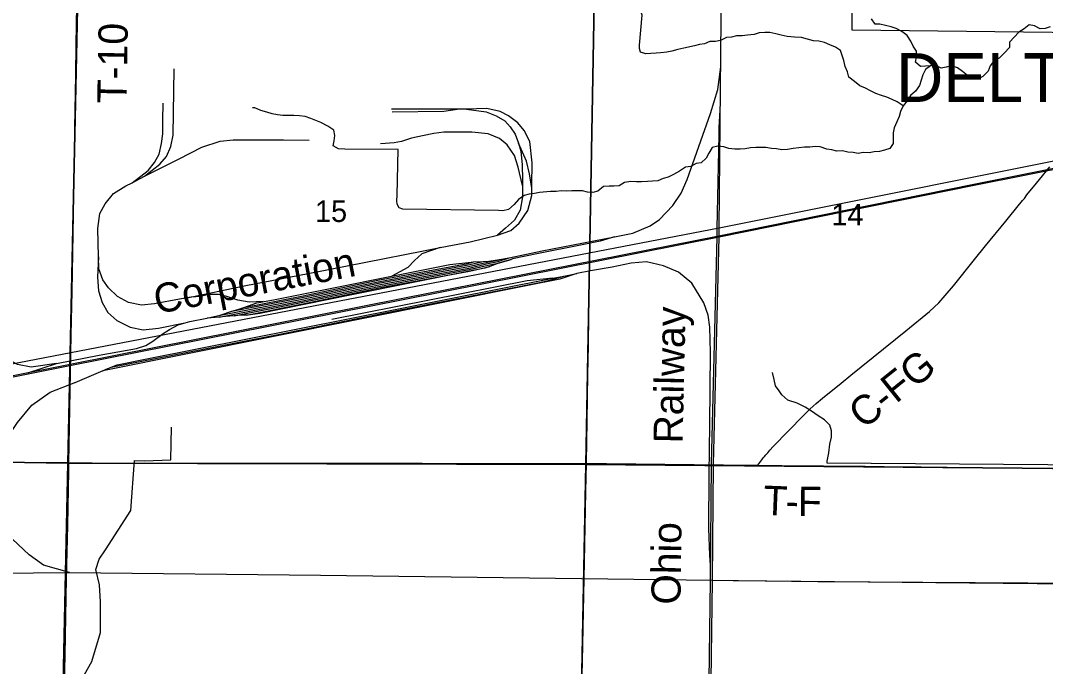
# Model space of a CAD drawing. Extents: x 0 to 42, y 0 to 22.
# Drawn here: x 3.119 to 5.107, y 16.093 to 17.347 of the extents above; entities that cross this region are included whole.
import ezdxf

# ---------------------------------------------------------------- set-up
doc = ezdxf.new("R2010")
doc.units = 0
for name, color, linetype in [('GM_X_Corporation', 7, 'Continuous'), ('GM_X_Corporation_Text', 7, 'Continuous'), ('GM_X_County_Road', 7, 'Continuous'), ('GM_X_County_Road_Text', 7, 'Continuous'), ('GM_X_Minor_River', 7, 'Continuous'), ('GM_X_Rail_Line', 7, 'Continuous'), ('GM_X_Rail_Line_Text', 7, 'Continuous'), ('GM_X_Section', 7, 'Continuous'), ('GM_X_Section_Text', 7, 'Continuous'), ('GM_X_Township_Road', 7, 'Continuous'), ('GM_X_Township_Road_Text', 7, 'Continuous')]:
    doc.layers.add(name, color=color, linetype=linetype)

msp = doc.modelspace()

# ---------------------------------------------------------------- linework, layer by layer
at = {"layer": 'GM_X_Corporation'}
msp.add_lwpolyline([(5.2302, 17.3226), (4.7322, 17.3283), (4.7317, 17.4841)], dxfattribs=at)
at = {"layer": 'GM_X_County_Road'}
for points in [[(4.5493, 16.4842), (4.557, 16.4944), (4.5595, 16.498), (4.5622, 16.501), (4.5648, 16.5039), (4.5685, 16.5081), (4.5724, 16.513), (4.5787, 16.52), (4.6373, 16.5802), (4.6507, 16.5932), (4.6622, 16.6037), (4.6741, 16.6138), (4.7104, 16.6431), (4.7296, 16.6589), (4.8363, 16.7446), (4.8821, 16.782), (4.8912, 16.7903), (4.8999, 16.7991), (4.9122, 16.8131), (4.9281, 16.8322), (4.9692, 16.883), (4.9907, 16.9096), (5.0298, 16.9578), (5.0376, 16.967), (5.0622, 16.9973), (5.0661, 17.0017), (5.0709, 17.0083), (5.0896, 17.0315), (5.1153, 17.0627)], [(2.209, 16.4644), (2.2212, 16.4668), (2.2731, 16.4767), (2.3584, 16.4941), (2.3767, 16.4974), (2.389, 16.499), (2.4013, 16.5001), (2.4137, 16.5007), (2.4355, 16.5009), (2.507, 16.4998), (2.5785, 16.4988), (2.6748, 16.4969), (2.8738, 16.4939), (2.9919, 16.4918), (3.0632, 16.491), (3.0779, 16.4906), (3.1679, 16.4894), (3.2134, 16.4891)], [(3.2134, 16.4891), (3.258, 16.4888), (3.373, 16.488), (3.4476, 16.4882), (3.4787, 16.4881), (3.5284, 16.488), (3.5937, 16.488), (3.6559, 16.4878), (3.7056, 16.4878), (3.7646, 16.4879), (3.8983, 16.4876), (3.9293, 16.4875), (4.0567, 16.4872), (4.0847, 16.4871), (4.2153, 16.4875), (4.2165, 16.4875)], [(4.2165, 16.4875), (4.2557, 16.4872), (4.4826, 16.4845), (4.5493, 16.4842)]]:
    msp.add_lwpolyline(points, dxfattribs=at)
at = {"layer": 'GM_X_Minor_River'}
for points in [[(4.3197, 17.2987), (4.3245, 17.3574), (4.3213, 17.3662), (4.3149, 17.369), (4.2953, 17.3748), (4.2312, 17.391), (4.2268, 17.3975), (4.2247, 17.4075), (4.2193, 17.4194), (4.1864, 17.4402), (4.1477, 17.4395)], [(4.8841, 17.2591), (4.8643, 17.2577), (4.8546, 17.2662), (4.8564, 17.2764), (4.8566, 17.2871), (4.8504, 17.2971), (4.8457, 17.307), (4.8384, 17.3178), (4.8283, 17.3253), (4.8175, 17.3316), (4.8077, 17.3345), (4.7858, 17.3395), (4.7763, 17.3397), (4.7693, 17.3501)], [(5.1161, 17.3348), (5.1062, 17.3316), (5.0967, 17.331), (5.0854, 17.3366), (5.0749, 17.3384), (5.0652, 17.3306), (5.0552, 17.3244), (5.0458, 17.3143), (5.0373, 17.3047), (5.0367, 17.2948), (5.0265, 17.2836), (5.0172, 17.2736), (5.0076, 17.2696), (4.9998, 17.2592), (4.9954, 17.2487), (4.9856, 17.2382), (4.9753, 17.2328), (4.9655, 17.2353), (4.9557, 17.2404), (4.946, 17.2482), (4.9363, 17.2553), (4.9239, 17.259), (4.914, 17.2562), (4.9044, 17.2545)], [(4.8306, 17.181), (4.8194, 17.1888), (4.8093, 17.1936), (4.7992, 17.198), (4.7886, 17.2013), (4.7777, 17.2053), (4.7676, 17.2101), (4.7575, 17.2153), (4.7466, 17.2204), (4.7365, 17.2286), (4.7257, 17.2372), (4.7229, 17.2475), (4.7182, 17.2575), (4.7155, 17.269), (4.7123, 17.2789), (4.7091, 17.2888), (4.6994, 17.2951), (4.6889, 17.2999), (4.678, 17.304), (4.6674, 17.3069), (4.6568, 17.3075), (4.6451, 17.3104), (4.6334, 17.3137), (4.6198, 17.3144), (4.6062, 17.3158), (4.5945, 17.3187), (4.5839, 17.3212), (4.5722, 17.3234), (4.5627, 17.3236), (4.5517, 17.3227), (4.5421, 17.3195), (4.5288, 17.3183), (4.5185, 17.317), (4.5079, 17.3169), (4.498, 17.3144), (4.4881, 17.3139), (4.4766, 17.3081), (4.4671, 17.306), (4.4561, 17.3063), (4.4457, 17.3019), (4.4362, 17.3003), (4.4263, 17.2978), (4.4057, 17.293), (4.3942, 17.2906), (4.3824, 17.2874), (4.3725, 17.2854), (4.3604, 17.2843), (4.3516, 17.2835), (4.3413, 17.283), (4.3318, 17.2821), (4.3217, 17.2854), (4.3196, 17.2924), (4.3197, 17.2987)], [(4.9044, 17.2545), (4.8943, 17.2593), (4.8841, 17.2591), (4.8744, 17.2521), (4.8689, 17.2416), (4.866, 17.2311), (4.8627, 17.2205), (4.8548, 17.21), (4.8452, 17.2012), (4.8385, 17.1907), (4.8306, 17.181), (4.8258, 17.1701), (4.823, 17.1603), (4.8186, 17.1505), (4.8134, 17.1389), (4.8112, 17.1287), (4.8114, 17.118), (4.8115, 17.1085), (4.8052, 17.0984), (4.7949, 17.0952), (4.785, 17.0928), (4.7747, 17.0923), (4.7648, 17.0902), (4.7534, 17.0905), (4.7435, 17.0888), (4.7337, 17.0909), (4.7235, 17.0915), (4.7133, 17.0937), (4.7023, 17.0935), (4.6925, 17.096), (4.6826, 17.0974), (4.6702, 17.1015), (4.66, 17.1024), (4.6497, 17.1011), (4.6395, 17.101), (4.6288, 17.0997), (4.6174, 17.0988), (4.6064, 17.0968), (4.5953, 17.0959), (4.5855, 17.0977), (4.5753, 17.0986), (4.5643, 17.1004), (4.5549, 17.1006), (4.545, 17.1005), (4.5351, 17.0995), (4.5244, 17.0979), (4.5149, 17.097), (4.5043, 17.0972), (4.4926, 17.0986), (4.4828, 17.1015), (4.4714, 17.1029), (4.4604, 17.1004), (4.4541, 17.0896), (4.4489, 17.0795), (4.4392, 17.0709), (4.4297, 17.0693), (4.4189, 17.0638), (4.4086, 17.0621), (4.3971, 17.0548), (4.3856, 17.0478), (4.3752, 17.0428), (4.3656, 17.0403), (4.3549, 17.036), (4.3447, 17.0351), (4.3348, 17.0342), (4.3234, 17.0337), (4.3135, 17.0339), (4.3029, 17.0345), (4.2907, 17.0325), (4.2803, 17.0259), (4.2701, 17.0254), (4.2606, 17.0256), (4.2496, 17.0247), (4.2387, 17.0158), (4.2288, 17.013), (4.2186, 17.0136), (4.2088, 17.0161), (4.1883, 17.0166), (4.1784, 17.0157), (4.1674, 17.0163), (4.1579, 17.015), (4.1469, 17.0148), (4.1256, 17.013), (4.1157, 17.0114), (4.1058, 17.0101), (4.0959, 17.0073), (4.0851, 16.9995), (4.0765, 16.9899), (4.0655, 16.9799), (4.0546, 16.9777), (4.0459, 16.978)], [(3.7485, 17.097), (3.7361, 17.098), (3.7259, 17.1036), (3.7277, 17.1134), (3.7287, 17.1236), (3.727, 17.1339), (3.7154, 17.1418), (3.7016, 17.1489), (3.682, 17.1569), (3.6711, 17.1606), (3.6605, 17.1616), (3.6495, 17.1626), (3.6382, 17.1625), (3.6283, 17.1627), (3.6177, 17.1637), (3.6071, 17.1658), (3.5973, 17.1691), (3.5856, 17.1724), (3.574, 17.1776), (3.5691, 17.1777)], [(4.0459, 16.978), (3.8604, 16.9806), (3.8533, 16.9835), (3.8496, 16.9907), (3.849, 16.9972), (3.8497, 17.0078), (3.8517, 17.0966), (3.7485, 17.097)], [(5.453, 16.482), (4.6837, 16.4882), (4.6837, 16.492), (4.6864, 16.5079), (4.6887, 16.5249), (4.692, 16.5381), (4.6919, 16.5506), (4.6888, 16.5617), (4.6784, 16.5718), (4.6661, 16.5797), (4.6534, 16.5887), (4.6406, 16.5966), (4.6256, 16.6041), (4.6072, 16.6102), (4.5957, 16.6203), (4.5905, 16.6284), (4.5832, 16.6381), (4.5804, 16.6503), (4.5773, 16.664)], [(3.36, 16.4927), (3.4109, 16.4946), (3.412, 16.5576)], [(2.699, 15.4505), (2.7058, 15.4647), (2.7257, 15.4696), (2.7455, 15.4741), (2.7645, 15.4756), (2.7816, 15.4752), (3.0251, 15.4747), (3.0476, 15.495), (3.1804, 15.4958), (3.1937, 16.0334), (3.2149, 16.047), (3.2374, 16.0677), (3.2576, 16.1033), (3.2748, 16.1595), (3.2747, 16.2191), (3.2728, 16.2518), (3.2652, 16.2815), (3.2721, 16.3019), (3.2839, 16.3195), (3.3331, 16.3958), (3.3403, 16.4932), (3.36, 16.4927)], [(5.3527, 16.2512), (4.5012, 16.2596)]]:
    msp.add_lwpolyline(points, dxfattribs=at)
at = {"layer": 'GM_X_Rail_Line'}
for p, q in [((3.9844, 17.175), (3.9704, 17.175)), ((3.3356, 17.0321), (3.3598, 17.0445)), ((3.998, 16.8783), (4.0163, 16.8794)), ((4.048, 16.8833), (4.0667, 16.8862)), ((4.173, 16.8509), (4.1981, 16.8559)), ((4.1514, 16.8466), (4.173, 16.8509)), ((3.5045, 16.7713), (3.4811, 16.7692)), ((3.279, 16.6673), (3.2247, 16.6441)), ((2.8633, 16.272), (3.2142, 16.2756))]:
    msp.add_line(p, q, dxfattribs=at)
for points in [[(4.4201, 14.1), (4.4258, 14.4841), (4.4505, 15.4825), (4.4609, 16.2603), (4.4628, 16.4862), (4.4739, 16.927), (4.4741, 16.9438), (4.4795, 17.4845), (4.5072, 18.7551), (4.5183, 19.5978), (4.5387, 20.5461), (4.5449, 20.9)], [(2.1, 16.459), (2.2129, 16.4808), (2.5454, 16.5465), (3.2154, 16.6797), (3.8608, 16.8081), (4.4734, 16.9293), (4.9678, 17.0293), (5.6609, 17.1675), (6.33, 17.2984), (6.9548, 17.4275), (7.5722, 17.5495), (8.2054, 17.6814), (8.8625, 17.8098), (8.9, 17.8172)], [(2.1, 16.4567), (2.2123, 16.4784), (2.5452, 16.5433), (3.215, 16.6775), (3.8612, 16.8058), (4.4739, 16.927), (4.9682, 17.0271), (5.6614, 17.1653), (6.3305, 17.2961), (6.9553, 17.4252), (7.5727, 17.5472), (8.2058, 17.6791), (8.8629, 17.8076), (8.9, 17.8149)], [(4.4738, 16.9443), (5.2911, 17.1083), (5.3521, 17.1586), (5.3953, 17.2101), (5.4468, 17.276), (5.4779, 17.3324), (5.5342, 17.3923), (5.5893, 17.4474), (5.618, 17.4689), (5.6635, 17.4809), (6.1368, 17.4838), (6.5418, 17.4827), (6.748, 17.4796), (7.1583, 17.4796), (7.645, 17.5773), (8.6737, 17.7802), (8.9, 17.8248)], [(3.3598, 17.0445), (3.3897, 17.0679), (3.4024, 17.0831), (3.4106, 17.1024), (3.4151, 17.1242), (3.4176, 17.2532)], [(4.2709, 16.927), (4.3066, 16.9345), (4.3403, 16.9485), (4.3584, 16.9608), (4.3839, 16.988), (4.4003, 17.0118), (4.4118, 17.0381), (4.4571, 17.1664), (4.4717, 17.2129), (4.4772, 17.2569)], [(3.3356, 17.0321), (3.3666, 17.056), (3.3794, 17.0716), (3.3884, 17.0872), (3.3925, 17.1082), (3.3954, 17.1267), (3.3954, 17.1534), (3.3962, 17.1863)], [(3.9704, 17.175), (3.9347, 17.1747), (3.8389, 17.1747)], [(3.9704, 17.175), (3.9404, 17.1702), (3.8397, 17.169)], [(4.1109, 17.0218), (4.111, 17.0276), (4.1114, 17.0708), (4.1069, 17.1123), (4.0958, 17.1336), (4.0834, 17.1484), (4.0658, 17.1616), (4.0497, 17.1706), (4.0234, 17.176), (4.0033, 17.1752), (3.9844, 17.175)], [(3.9844, 17.175), (4.0222, 17.1698), (4.0419, 17.162), (4.0584, 17.1521), (4.0691, 17.1406), (4.0785, 17.1262), (4.0847, 17.109)], [(4.436, 14.8964), (4.4332, 14.9355), (4.4468, 15.4826), (4.4572, 16.2603), (4.4591, 16.4863), (4.4702, 16.9271), (4.4703, 16.9438), (4.4738, 17.1251), (4.4738, 17.1392), (4.4763, 17.1728)], [(3.3598, 17.0445), (3.4267, 17.0786), (3.471, 17.1008), (3.5068, 17.1127), (3.5315, 17.1151), (3.6293, 17.1156), (3.6794, 17.1147)], [(4.0926, 17.0264), (4.0843, 17.0625), (4.0773, 17.0851), (4.0633, 17.1053), (4.0481, 17.1176), (4.0259, 17.1267), (3.9943, 17.1304), (3.9404, 17.1299), (3.9207, 17.1275), (3.8989, 17.123), (3.8775, 17.1184), (3.8582, 17.1119), (3.8442, 17.1094), (3.8171, 17.1077)], [(4.1109, 17.0218), (4.1061, 17.0494), (4.1003, 17.074), (4.0847, 17.109)], [(4.0847, 17.109), (4.0892, 17.0934), (4.0921, 17.0671), (4.0925, 17.0379), (4.0926, 17.0264)], [(3.2705, 16.8883), (3.2692, 16.9433), (3.2733, 16.9725), (3.2836, 16.9914), (3.2996, 17.0112), (3.3235, 17.026), (3.3356, 17.0321)], [(4.0926, 17.0264), (4.0929, 17.0046), (4.088, 16.9787), (4.0769, 16.9594), (4.0596, 16.9438), (4.0444, 16.9306)], [(4.0444, 16.9306), (4.0699, 16.9396), (4.0863, 16.9536), (4.1028, 16.9783), (4.1106, 17.007), (4.1109, 17.0218)], [(2.1, 16.4779), (3.0648, 16.6733), (4.4738, 16.9443)], [(3.9331, 16.9061), (3.9914, 16.9174), (4.0444, 16.9306)], [(4.0667, 16.8862), (4.1308, 16.9), (4.2709, 16.927), (4.2436, 16.9185), (4.2055, 16.9109), (4.1239, 16.8948), (4.0736, 16.8843), (4.0705, 16.8833)], [(3.4394, 16.808), (3.5565, 16.8324), (3.6774, 16.8562), (3.9005, 16.8998), (3.9331, 16.9061)], [(3.9331, 16.9061), (3.8977, 16.8944), (3.8833, 16.8809), (3.8705, 16.8677), (3.8549, 16.8591), (3.8391, 16.8507)], [(3.2705, 16.8883), (3.2684, 16.8488), (3.2705, 16.8221), (3.2779, 16.7999), (3.289, 16.7802), (3.3062, 16.7646), (3.3317, 16.7518), (3.3572, 16.7465), (3.3872, 16.7498), (3.438, 16.76)], [(3.4394, 16.808), (3.4279, 16.8061), (3.3794, 16.797), (3.3543, 16.7946), (3.3288, 16.7995), (3.3075, 16.811), (3.2902, 16.8283), (3.2791, 16.8435), (3.2713, 16.8653), (3.2705, 16.8883)], [(3.5039, 16.7744), (3.6653, 16.8061), (3.8165, 16.8377), (3.9878, 16.8695), (4.0246, 16.8781), (4.0442, 16.882), (4.048, 16.8833)], [(3.5045, 16.7713), (3.6659, 16.803), (3.8171, 16.8346), (3.9884, 16.8665), (4.0253, 16.8751), (4.045, 16.879), (4.0667, 16.8862)], [(3.5294, 16.7826), (3.6647, 16.8091), (3.8159, 16.8407), (3.9872, 16.8726), (4.0163, 16.8794)], [(3.5334, 16.7738), (3.6665, 16.8), (3.8177, 16.8316), (3.9891, 16.8635), (4.0259, 16.872), (4.0458, 16.876), (4.0705, 16.8833)], [(3.5524, 16.7902), (3.5778, 16.7991), (3.6097, 16.8047), (3.952, 16.8734), (3.9931, 16.878), (3.998, 16.8783)], [(3.5524, 16.7902), (3.664, 16.8122), (3.8153, 16.8438), (3.9865, 16.8756), (3.998, 16.8783)], [(4.0163, 16.8794), (4.0272, 16.88), (4.048, 16.8833)], [(4.0705, 16.8833), (4.048, 16.8764), (4.0291, 16.8695)], [(4.4574, 16.29), (4.4558, 16.3092), (4.4542, 16.3614), (4.4546, 16.4666), (4.4558, 16.5623), (4.4575, 16.7025), (4.4562, 16.7518), (4.4529, 16.7752), (4.4443, 16.7991), (4.4209, 16.8369), (4.3954, 16.8583), (4.3658, 16.871), (4.3329, 16.8784), (4.3033, 16.8763), (4.2663, 16.8685), (4.2244, 16.8611), (4.1981, 16.8559)], [(4.1981, 16.8559), (4.165, 16.8449), (4.1032, 16.8324), (3.279, 16.6673)], [(3.5577, 16.7754), (3.6671, 16.797), (3.8183, 16.8285), (3.9897, 16.8604), (4.0266, 16.869), (4.0291, 16.8695)], [(4.0291, 16.8695), (4.02, 16.8662), (3.9868, 16.8596), (3.7616, 16.8146), (3.5837, 16.7784), (3.5656, 16.7758), (3.5577, 16.7754)], [(3.2951, 16.6742), (3.6222, 16.7381), (3.8427, 16.7828), (4.1287, 16.8393), (4.1482, 16.8434), (4.173, 16.8509)], [(3.2951, 16.6742), (3.3066, 16.679), (3.3613, 16.6897), (4.1514, 16.8466)], [(4.1514, 16.8466), (4.1015, 16.8414), (3.723, 16.7666)], [(3.5901, 16.8013), (3.5627, 16.8003), (3.5405, 16.804), (3.5195, 16.8114), (3.5035, 16.8155), (3.4842, 16.8151), (3.4682, 16.8114), (3.4501, 16.8098), (3.4394, 16.808)], [(3.1334, 16.6634), (3.1894, 16.6814), (3.2716, 16.6972), (3.344, 16.7106), (3.3621, 16.7162), (3.3762, 16.7245), (3.3963, 16.7393), (3.4081, 16.7471), (3.4249, 16.7564), (3.4476, 16.7626), (3.4808, 16.7692), (3.5064, 16.7751), (3.5294, 16.7826)], [(3.5294, 16.7826), (3.5429, 16.7869), (3.5524, 16.7902)], [(3.5577, 16.7754), (3.5485, 16.7751), (3.5334, 16.7738)], [(3.5334, 16.7738), (3.5169, 16.7725), (3.5045, 16.7713)], [(3.1894, 16.6814), (3.1399, 16.6744), (3.1133, 16.6792), (3.0903, 16.6915), (3.0656, 16.708)], [(3.279, 16.6673), (3.284, 16.6695), (3.2951, 16.6742)], [(3.0848, 16.502), (3.0944, 16.538), (3.1136, 16.5667), (3.1411, 16.6003), (3.1771, 16.6255), (3.2266, 16.6448)], [(3.2142, 16.2756), (3.1639, 16.29), (3.1363, 16.3103), (3.104, 16.3403), (3.0872, 16.3714), (3.0777, 16.405), (3.0741, 16.4385), (3.0777, 16.4685), (3.0848, 16.502)], [(3.2142, 16.2756), (3.7011, 16.2705), (4.4607, 16.2608)], [(4.4607, 16.2608), (4.6655, 16.258), (5.6831, 16.252), (6.101, 16.2418), (7.4287, 16.222), (8.568, 16.211), (8.9, 16.2074)]]:
    msp.add_lwpolyline(points, dxfattribs=at)
at = {"layer": 'GM_X_Section'}
for points in [[(3.2323, 17.4917), (3.2111, 16.4878), (2.2056, 16.5033), (2.2245, 17.5054)], [(4.2338, 17.4876), (4.2153, 16.4855), (3.2111, 16.4878), (3.2323, 17.4917)], [(5.2334, 17.4797), (5.2156, 16.4769), (4.2153, 16.4855), (4.2338, 17.4876)], [(2.2056, 16.5033), (3.2111, 16.4878), (3.1895, 15.4854), (2.1886, 15.5005)], [(3.2111, 16.4878), (4.2153, 16.4855), (4.1963, 15.4797), (3.1895, 15.4854)], [(4.2153, 16.4855), (5.2156, 16.4769), (5.2026, 15.4687), (4.1963, 15.4797)]]:
    msp.add_lwpolyline(points, close=True, dxfattribs=at)
at = {"layer": 'GM_X_Township_Road'}
for points in [[(3.2134, 16.4891), (3.2159, 16.6283), (3.2177, 16.7371), (3.2195, 16.8211), (3.2214, 16.933), (3.2241, 17.0853), (3.2249, 17.1381), (3.2265, 17.2407), (3.2275, 17.2998), (3.2292, 17.4148), (3.2301, 17.4677), (3.2306, 17.4912)], [(4.2165, 16.4875), (4.2165, 16.489), (4.2172, 16.5294), (4.2179, 16.5698), (4.2196, 16.66), (4.2204, 16.716), (4.2214, 16.775), (4.2223, 16.8527)], [(2.209, 16.4644), (2.2212, 16.4668), (2.2731, 16.4767), (2.3584, 16.4941), (2.3767, 16.4974), (2.389, 16.499), (2.4013, 16.5001), (2.4137, 16.5007), (2.4355, 16.5009), (2.507, 16.4998), (2.5785, 16.4988), (2.6748, 16.4969), (2.8738, 16.4939), (2.9919, 16.4918), (3.0632, 16.491), (3.0779, 16.4906), (3.1679, 16.4894), (3.2134, 16.4891)], [(3.1925, 15.4887), (3.1938, 15.5436), (3.1954, 15.615), (3.1966, 15.6834), (3.1999, 15.8264), (3.2025, 15.9476), (3.2029, 15.9881), (3.2039, 16.0316), (3.2057, 16.1155), (3.208, 16.2274), (3.2088, 16.2647), (3.2109, 16.3672), (3.2131, 16.4729), (3.2134, 16.4891)], [(3.2134, 16.4891), (3.258, 16.4888), (3.373, 16.488), (3.4476, 16.4882), (3.4787, 16.4881), (3.5284, 16.488), (3.5937, 16.488), (3.6559, 16.4878), (3.7056, 16.4878), (3.7646, 16.4879), (3.8983, 16.4876), (3.9293, 16.4875), (4.0567, 16.4872), (4.0847, 16.4871), (4.2153, 16.4875), (4.2165, 16.4875)], [(4.2067, 15.9906), (4.2077, 16.0508), (4.2089, 16.1037), (4.2128, 16.2964), (4.2153, 16.4331), (4.2165, 16.4875)], [(4.2165, 16.4875), (4.2557, 16.4872), (4.4826, 16.4845), (4.5493, 16.4842)], [(4.5493, 16.4842), (4.5955, 16.4835), (4.757, 16.4818), (4.7943, 16.4814), (4.8657, 16.4805), (5.0676, 16.478), (5.1204, 16.4777), (5.2446, 16.4769), (5.3565, 16.4774), (5.4838, 16.4794), (5.6235, 16.481), (5.6608, 16.4814), (5.7882, 16.4826), (5.931, 16.4842), (6.0428, 16.4844), (6.0832, 16.4848), (6.0936, 16.4849)]]:
    msp.add_lwpolyline(points, dxfattribs=at)

# ---------------------------------------------------------------- texts
at = {"layer": 'GM_X_Corporation_Text'}
msp.add_text('DELTA', height=0.0947, rotation=0, dxfattribs=at).set_placement((4.8172, 17.1888))
at = {"layer": 'GM_X_County_Road_Text'}
msp.add_text('C-FG', height=0.05682, rotation=38.8016, dxfattribs=at).set_placement((4.7544, 16.5523))
at = {"layer": 'GM_X_Rail_Line_Text'}
for s, height, rotation, p in [('Corporation', 0.056629, 10.849, (3.3838, 16.7772)), ('Railway', 0.05663, 88.7615, (4.4032, 16.5258)), ('Ohio', 0.05663, 89.2367, (4.399, 16.2132))]:
    msp.add_text(s, height=height, rotation=rotation, dxfattribs=at).set_placement(p)
at = {"layer": 'GM_X_Section_Text'}
for s, p in [('15', (3.6904, 16.9559)), ('14', (4.6916, 16.9491))]:
    msp.add_text(s, height=0.04186, rotation=0, dxfattribs=at).set_placement(p)
at = {"layer": 'GM_X_Township_Road_Text'}
for s, height, rotation, p in [('T-10', 0.05682, 88.9454, (3.3248, 17.1855)), ('T', 0.0568, 357.758, (4.5588, 16.3878)), ('F', 0.0568, 359.296, (4.6262, 16.3857)), ('-', 0.0568, 358.9555, (4.6025, 16.3861))]:
    msp.add_text(s, height=height, rotation=rotation, dxfattribs=at).set_placement(p)

doc.saveas('drawing.dxf')
